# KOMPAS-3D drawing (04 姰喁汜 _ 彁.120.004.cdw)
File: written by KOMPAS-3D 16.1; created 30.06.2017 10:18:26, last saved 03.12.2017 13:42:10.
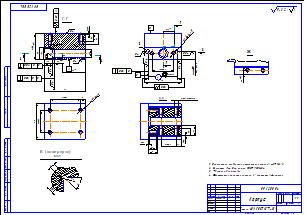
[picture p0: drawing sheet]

Sheet 1: A2, landscape

Title block, sheet 1: name: Корпус; designation: ПР.120.004; material: Сталь 40Х ГОСТ 1577-81; scale: 1:1; sheets: 1; sheet format: A2; stored path: C:\Users\2\Desktop\SIS70\Прохвост\Корпус _ К17.479.004.cdw; drawn by: Сигачев СИ

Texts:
  Сигачев
  romans
  Е (повернуто)
  с 2-х сторон
  Неуказанные предельные отклонения размеров   (IT 14)/2.
  Покрытие: Хим. Окс. прм по ГОСТ 9.303-84.
  * Размеры для справок.
  Фактическое значение размера "а" записать в формуляр.
  Ra3,2
  Ra3,2 ( )
  CONTINUOUS_RGB_0_0_0_THICK_0.18
  CONTINUOUS_RGB_0_0_255_THICK_0.18
  CONTINUOUS_RGB_0_255_0_THICK_0.18
Dimensions and other numbers on the sheet: 3; 9; 1; 15; 20; 0,4; 0,02; 0,2; 12±0,1; 24; 50; 4,2; 45; 80; 14; -7Н; 4 отв.; 8±0,1; 43±0,1; 72; 60±0,1; 10; 7,5; 2; 1,6; 0,5; 21,5; 42±0,1; 58; 2 отв.; 30±0,1; 18; 0,04; 1:1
